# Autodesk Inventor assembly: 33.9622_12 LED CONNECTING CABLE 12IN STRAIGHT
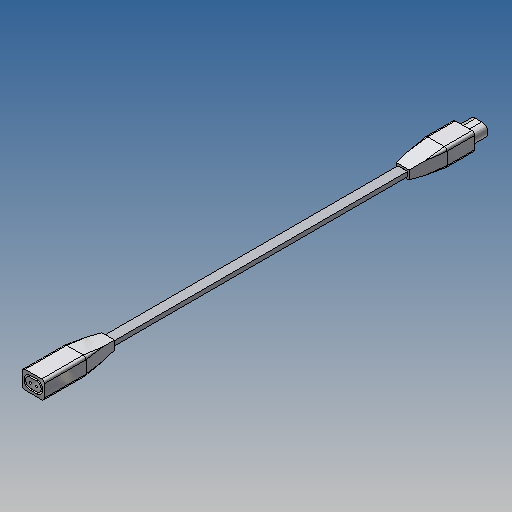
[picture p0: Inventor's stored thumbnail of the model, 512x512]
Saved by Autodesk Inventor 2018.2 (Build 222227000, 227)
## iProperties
Created: 2018-05
Part Number: 33.9622_12 LED CONNECTING CABLE 12IN STRAIGHT
Document SubType Name: Assembly
Designer: amoles
Author: amoles
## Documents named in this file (4)
- Y:\INVENTOR LIBRARIES\PARTS LIBRARY\WORKSTATION\LIGHTS OUTWATER PLASTICS\33.9622_12 LED CONNECTING CABLE 12IN STRAIGHT.iam
- Y:\INVENTOR LIBRARIES\PARTS LIBRARY\WORKSTATION\LIGHTS OUTWATER PLASTICS\SUBCOMPONENTS\33.9622 PLUG END FEMALE.ipt
- Y:\INVENTOR LIBRARIES\PARTS LIBRARY\WORKSTATION\LIGHTS OUTWATER PLASTICS\SUBCOMPONENTS\33.9622 PLUG END MALE.ipt
- Y:\INVENTOR LIBRARIES\PARTS LIBRARY\WORKSTATION\LIGHTS OUTWATER PLASTICS\SUBCOMPONENTS\33.9622_12 CORD STRAIGHT.ipt
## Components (3 placed, 3 different names)
1. 33.9622 PLUG END FEMALE:1 — Mate:1, Mate:2, Mate:3
2. 33.9622 PLUG END MALE:1 — Mate:4, Mate:5, Mate:6
3. 33.9622_12 CORD STRAIGHT:1 — Mate:1, Mate:2, Mate:3, Mate:4, Mate:5, Mate:6
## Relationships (6: Mate 6)
- Mate:1: 33.9622 PLUG END FEMALE:1 ↔ 33.9622_12 CORD STRAIGHT:1
- Mate:2: 33.9622 PLUG END FEMALE:1 ↔ 33.9622_12 CORD STRAIGHT:1
- Mate:3: 33.9622 PLUG END FEMALE:1 ↔ 33.9622_12 CORD STRAIGHT:1
- Mate:4: 33.9622 PLUG END MALE:1 ↔ 33.9622_12 CORD STRAIGHT:1
- Mate:5: 33.9622 PLUG END MALE:1 ↔ 33.9622_12 CORD STRAIGHT:1
- Mate:6: 33.9622 PLUG END MALE:1 ↔ 33.9622_12 CORD STRAIGHT:1
